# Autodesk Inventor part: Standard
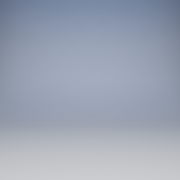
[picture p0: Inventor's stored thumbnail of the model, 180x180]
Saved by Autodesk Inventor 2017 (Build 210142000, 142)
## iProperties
Created: 2005-05
Part Number: Standard
Document SubType Name: Modeling
Designer: JWe
Density: 1 g/cm^3
Material: Generic
Appearance: Default
Author: JWe
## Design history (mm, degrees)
